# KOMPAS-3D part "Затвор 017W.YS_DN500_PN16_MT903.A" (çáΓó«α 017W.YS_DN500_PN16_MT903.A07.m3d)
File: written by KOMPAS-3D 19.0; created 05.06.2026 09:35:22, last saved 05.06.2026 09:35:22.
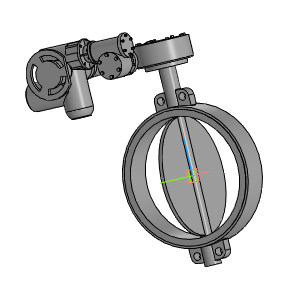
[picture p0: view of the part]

Document properties: Автор: Энергия; Полное имя файла: ..\..\..\3d для проектировщиков\x.x Тип 017W.Y(S) Затвор дисковый поворотный межфланцевый\Затвор 017W.Y(S)_DN32-DN1200_QT.A_MT903.A\Затвор 017W.YS_DN500_PN16_MT903.A07.a3d

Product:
- Part/product: Затвор 017W.YS_DN500_PN16_MT903.A
    Масса: 223.374

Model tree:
1. Операция без истории:1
